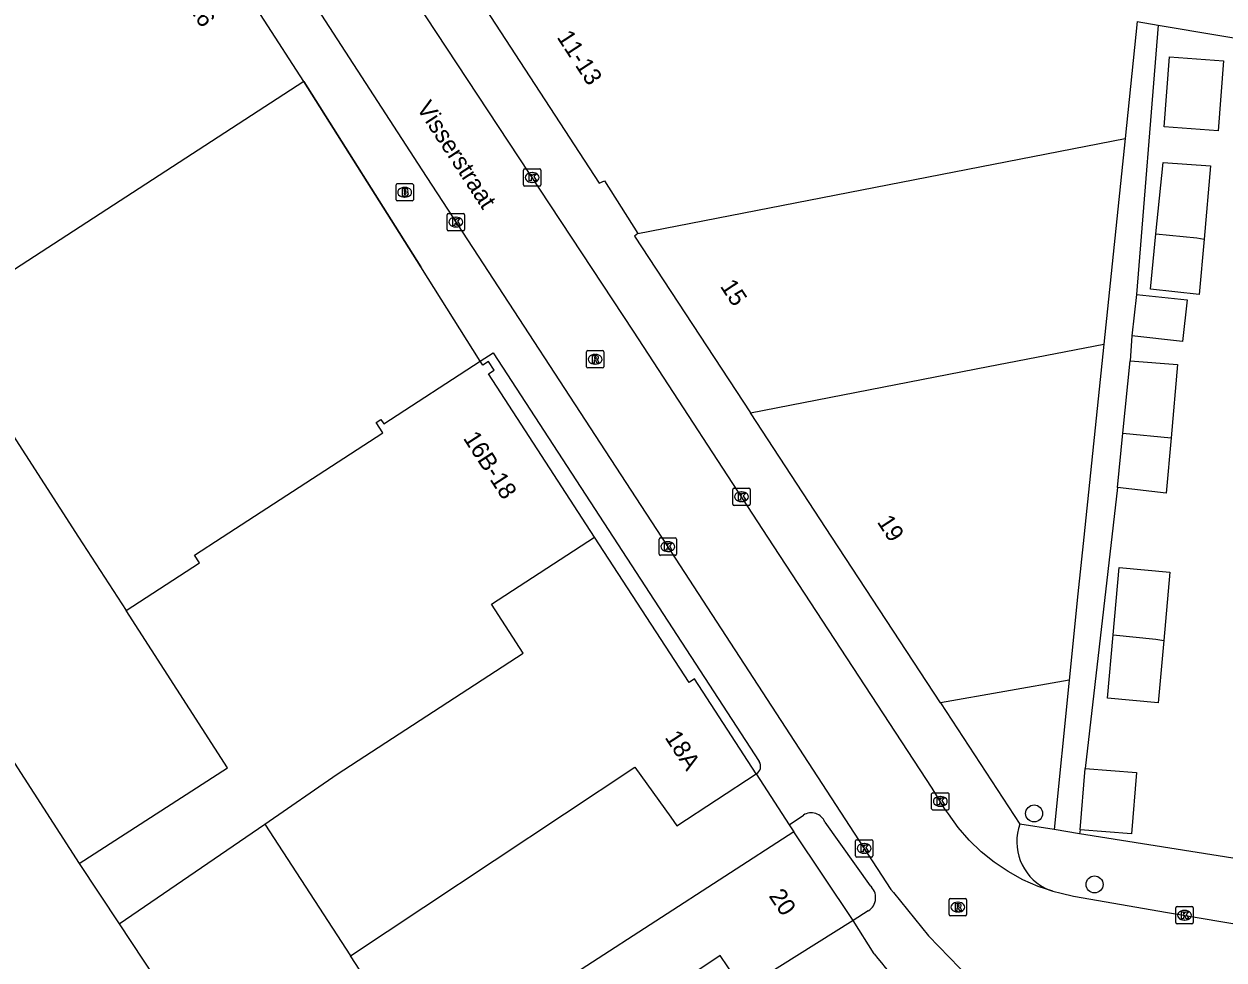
# Model space of a CAD drawing. Extents: x 160861 to 161308, y 384024 to 384878.
# Drawn here: x 161083.4 to 161152.6, y 384475.6 to 384529.6 of the extents above; entities that cross this region are included whole.
import ezdxf

# ---------------------------------------------------------------- set-up
doc = ezdxf.new("R2010")
doc.units = 0
for name, color, linetype in [('IMGEO_Boom', 7, 'Continuous'), ('IMGEO_Brandkraan', 7, 'Continuous'), ('IMGEO_Kolk', 7, 'Continuous'), ('IMGEO_Muur', 7, 'Continuous'), ('IMGEO_Openbare_ruimte_label', 7, 'Continuous'), ('IMGEO_Pand', 7, 'Continuous'), ('IMGEO_Pand_nummerreeks', 7, 'Continuous'), ('IMGEO_Parkeervlak_open', 7, 'Continuous'), ('IMGEO_Rijbaan_lokaal_open', 7, 'Continuous'), ('IMGEO_Rioolput', 7, 'Continuous'), ('IMGEO_Voetpad_open', 7, 'Continuous')]:
    doc.layers.add(name, color=color, linetype=linetype)

msp = doc.modelspace()

# ---------------------------------------------------------------- linework, layer by layer
at = {"layer": 'IMGEO_Boom'}
for centre in [(161141.654, 384484.053), (161145.139, 384479.956)]:
    msp.add_circle(centre, 0.489, dxfattribs=at)
at = {"layer": 'IMGEO_Brandkraan'}
for p, q in [((161104.842, 384519.474), (161104.842, 384520.326)), ((161104.917, 384520.4), (161105.769, 384520.4)), ((161105.33, 384520.18), (161105.355, 384520.18)), ((161105.843, 384520.326), (161105.843, 384519.474)), ((161105.353, 384519.62), (161105.328, 384519.62)), ((161105.769, 384519.4), (161104.917, 384519.4))]:
    msp.add_line(p, q, dxfattribs=at)
for points in [[(161104.842, 384519.474), (161104.842, 384520.326)], [(161104.917, 384520.4), (161105.769, 384520.4)], [(161105.843, 384520.326), (161105.843, 384519.474)], [(161105.19, 384520.1), (161105.19, 384519.7), (161105.403, 384519.7)], [(161105.421, 384520.1), (161105.19, 384520.1)], [(161105.369, 384520.019), (161105.315, 384520.019), (161105.315, 384519.943)], [(161105.315, 384519.943), (161105.368, 384519.943)], [(161105.377, 384519.867), (161105.315, 384519.867), (161105.315, 384519.786)], [(161105.315, 384519.786), (161105.377, 384519.786)], [(161105.769, 384519.4), (161104.917, 384519.4)]]:
    msp.add_lwpolyline(points, dxfattribs=at)
for centre, radius, start, end in [((161104.919, 384520.324), 0.0765, 91.55205, 178.44795), ((161104.919, 384520.324), 0.0765, 91.55205, 178.44795), ((161105.767, 384520.324), 0.0765, 1.55205, 88.44795), ((161105.767, 384520.324), 0.0765, 1.55205, 88.44795), ((161104.919, 384519.476), 0.0765, 181.55205, 268.44795), ((161104.919, 384519.476), 0.0765, 181.55205, 268.44795), ((161105.37, 384519.981), 0.0379, 267.82845, 90.93552), ((161105.378, 384519.826), 0.0404, 269.87594, 90.50774), ((161105.409, 384519.951), 0.251, 268.66757, 293.53466), ((161105.425, 384519.955), 0.145, 59.4692, 91.53667), ((161105.45, 384520.002), 0.0922, 285.51372, 58.15012), ((161105.455, 384519.81), 0.105, 301.31148, 78.98903), ((161105.767, 384519.476), 0.0765, 271.55205, 358.44795), ((161105.767, 384519.476), 0.0765, 271.55205, 358.44795)]:
    msp.add_arc(centre, radius, start, end, dxfattribs=at)
for centre, major_axis, ratio, start_param, end_param in [((161105.329, 384519.9), (-0.387, 0.002), 0.722429, 4.712389, 7.853982), ((161105.354, 384519.9), (-0.39, 0.002), 0.717154, 1.570796, 4.712389)]:
    msp.add_ellipse(centre, major_axis=major_axis, ratio=ratio, start_param=start_param, end_param=end_param, dxfattribs=at)
at = {"layer": 'IMGEO_Kolk'}
for p, q in [((161112.2, 384520.328), (161112.2, 384521.18)), ((161112.275, 384521.254), (161113.127, 384521.254)), ((161112.688, 384521.034), (161112.713, 384521.034)), ((161113.201, 384521.18), (161113.201, 384520.328)), ((161113.127, 384520.254), (161112.275, 384520.254)), ((161112.711, 384520.474), (161112.686, 384520.474)), ((161107.791, 384517.756), (161107.791, 384518.608)), ((161107.866, 384518.682), (161108.718, 384518.682)), ((161108.279, 384518.462), (161108.304, 384518.462)), ((161108.792, 384518.608), (161108.792, 384517.756)), ((161108.718, 384517.682), (161107.866, 384517.682)), ((161108.302, 384517.902), (161108.277, 384517.902)), ((161124.352, 384502.83), (161125.204, 384502.83)), ((161124.277, 384501.904), (161124.277, 384502.756)), ((161124.765, 384502.61), (161124.79, 384502.61)), ((161125.278, 384502.756), (161125.278, 384501.904)), ((161125.204, 384501.83), (161124.352, 384501.83)), ((161124.788, 384502.05), (161124.763, 384502.05)), ((161120.018, 384499.022), (161120.018, 384499.874)), ((161120.093, 384499.948), (161120.945, 384499.948)), ((161120.506, 384499.728), (161120.531, 384499.728)), ((161121.019, 384499.874), (161121.019, 384499.022)), ((161120.945, 384498.948), (161120.093, 384498.948)), ((161120.529, 384499.168), (161120.504, 384499.168)), ((161135.742, 384484.322), (161135.742, 384485.174)), ((161135.817, 384485.248), (161136.669, 384485.248)), ((161136.23, 384485.028), (161136.255, 384485.028)), ((161136.743, 384485.174), (161136.743, 384484.322)), ((161136.669, 384484.248), (161135.817, 384484.248)), ((161136.253, 384484.468), (161136.228, 384484.468)), ((161131.353, 384481.609), (161131.353, 384482.461)), ((161131.428, 384482.535), (161132.28, 384482.535)), ((161131.841, 384482.315), (161131.866, 384482.315)), ((161132.354, 384482.461), (161132.354, 384481.609)), ((161132.28, 384481.535), (161131.428, 384481.535)), ((161131.864, 384481.755), (161131.839, 384481.755)), ((161149.832, 384477.749), (161149.832, 384478.601)), ((161149.907, 384478.675), (161150.759, 384478.675)), ((161150.833, 384478.601), (161150.833, 384477.749)), ((161150.32, 384478.455), (161150.345, 384478.455)), ((161150.759, 384477.675), (161149.907, 384477.675)), ((161150.343, 384477.895), (161150.318, 384477.895))]:
    msp.add_line(p, q, dxfattribs=at)
for points in [[(161112.2, 384520.328), (161112.2, 384521.18)], [(161112.275, 384521.254), (161113.127, 384521.254)], [(161112.521, 384520.954), (161112.644, 384520.954), (161112.644, 384520.803), (161112.774, 384520.954), (161112.938, 384520.954), (161112.792, 384520.803), (161112.945, 384520.554), (161112.793, 384520.554), (161112.708, 384520.718), (161112.644, 384520.651), (161112.644, 384520.554), (161112.521, 384520.554), (161112.521, 384520.954)], [(161113.201, 384521.18), (161113.201, 384520.328)], [(161113.127, 384520.254), (161112.275, 384520.254)], [(161107.791, 384517.756), (161107.791, 384518.608)], [(161107.866, 384518.682), (161108.718, 384518.682)], [(161108.112, 384518.382), (161108.235, 384518.382), (161108.235, 384518.231), (161108.365, 384518.382), (161108.529, 384518.382), (161108.383, 384518.231), (161108.536, 384517.982), (161108.384, 384517.982), (161108.299, 384518.146), (161108.235, 384518.079), (161108.235, 384517.982), (161108.112, 384517.982), (161108.112, 384518.382)], [(161108.792, 384518.608), (161108.792, 384517.756)], [(161108.718, 384517.682), (161107.866, 384517.682)], [(161124.352, 384502.83), (161125.204, 384502.83)], [(161124.277, 384501.904), (161124.277, 384502.756)], [(161124.598, 384502.53), (161124.721, 384502.53), (161124.721, 384502.379), (161124.851, 384502.53), (161125.015, 384502.53), (161124.869, 384502.379), (161125.022, 384502.13), (161124.87, 384502.13), (161124.785, 384502.294), (161124.721, 384502.227), (161124.721, 384502.13), (161124.598, 384502.13), (161124.598, 384502.53)], [(161125.278, 384502.756), (161125.278, 384501.904)], [(161125.204, 384501.83), (161124.352, 384501.83)], [(161120.018, 384499.022), (161120.018, 384499.874)], [(161120.093, 384499.948), (161120.945, 384499.948)], [(161120.339, 384499.648), (161120.462, 384499.648), (161120.462, 384499.497), (161120.592, 384499.648), (161120.756, 384499.648), (161120.61, 384499.497), (161120.763, 384499.248), (161120.611, 384499.248), (161120.526, 384499.412), (161120.462, 384499.345), (161120.462, 384499.248), (161120.339, 384499.248), (161120.339, 384499.648)], [(161121.019, 384499.874), (161121.019, 384499.022)], [(161120.945, 384498.948), (161120.093, 384498.948)], [(161135.742, 384484.322), (161135.742, 384485.174)], [(161135.817, 384485.248), (161136.669, 384485.248)], [(161136.063, 384484.948), (161136.186, 384484.948), (161136.186, 384484.797), (161136.316, 384484.948), (161136.48, 384484.948), (161136.334, 384484.797), (161136.487, 384484.548), (161136.335, 384484.548), (161136.25, 384484.712), (161136.186, 384484.645), (161136.186, 384484.548), (161136.063, 384484.548), (161136.063, 384484.948)], [(161136.743, 384485.174), (161136.743, 384484.322)], [(161136.669, 384484.248), (161135.817, 384484.248)], [(161131.353, 384481.609), (161131.353, 384482.461)], [(161131.428, 384482.535), (161132.28, 384482.535)], [(161131.674, 384482.235), (161131.797, 384482.235), (161131.797, 384482.084), (161131.927, 384482.235), (161132.091, 384482.235), (161131.945, 384482.084), (161132.098, 384481.835), (161131.946, 384481.835), (161131.861, 384481.999), (161131.797, 384481.932), (161131.797, 384481.835), (161131.674, 384481.835), (161131.674, 384482.235)], [(161132.354, 384482.461), (161132.354, 384481.609)], [(161132.28, 384481.535), (161131.428, 384481.535)], [(161149.832, 384477.749), (161149.832, 384478.601)], [(161149.907, 384478.675), (161150.759, 384478.675)], [(161150.833, 384478.601), (161150.833, 384477.749)], [(161150.153, 384478.375), (161150.276, 384478.375), (161150.276, 384478.224), (161150.406, 384478.375), (161150.57, 384478.375), (161150.424, 384478.224), (161150.577, 384477.975), (161150.425, 384477.975), (161150.34, 384478.139), (161150.276, 384478.072), (161150.276, 384477.975), (161150.153, 384477.975), (161150.153, 384478.375)], [(161150.759, 384477.675), (161149.907, 384477.675)]]:
    msp.add_lwpolyline(points, dxfattribs=at)
for centre, start, end in [((161112.277, 384521.178), 91.55205, 178.44795), ((161112.277, 384521.178), 91.55205, 178.44795), ((161113.125, 384521.178), 1.55205, 88.44795), ((161113.125, 384521.178), 1.55205, 88.44795), ((161112.277, 384520.33), 181.55205, 268.44795), ((161112.277, 384520.33), 181.55205, 268.44795), ((161113.125, 384520.33), 271.55205, 358.44795), ((161113.125, 384520.33), 271.55205, 358.44795), ((161107.868, 384518.606), 91.55205, 178.44795), ((161107.868, 384518.606), 91.55205, 178.44795), ((161108.716, 384518.606), 1.55205, 88.44795), ((161108.716, 384518.606), 1.55205, 88.44795), ((161107.868, 384517.758), 181.55205, 268.44795), ((161107.868, 384517.758), 181.55205, 268.44795), ((161108.716, 384517.758), 271.55205, 358.44795), ((161108.716, 384517.758), 271.55205, 358.44795), ((161124.354, 384502.754), 91.55205, 178.44795), ((161124.354, 384502.754), 91.55205, 178.44795), ((161125.202, 384502.754), 1.55205, 88.44795), ((161125.202, 384502.754), 1.55205, 88.44795), ((161124.354, 384501.906), 181.55205, 268.44795), ((161124.354, 384501.906), 181.55205, 268.44795), ((161125.202, 384501.906), 271.55205, 358.44795), ((161125.202, 384501.906), 271.55205, 358.44795), ((161120.095, 384499.872), 91.55205, 178.44795), ((161120.095, 384499.872), 91.55205, 178.44795), ((161120.943, 384499.872), 1.55205, 88.44795), ((161120.943, 384499.872), 1.55205, 88.44795), ((161120.095, 384499.024), 181.55205, 268.44795), ((161120.095, 384499.024), 181.55205, 268.44795), ((161120.943, 384499.024), 271.55205, 358.44795), ((161120.943, 384499.024), 271.55205, 358.44795), ((161135.819, 384485.172), 91.55205, 178.44795), ((161135.819, 384485.172), 91.55205, 178.44795), ((161136.667, 384485.172), 1.55205, 88.44795), ((161136.667, 384485.172), 1.55205, 88.44795), ((161135.819, 384484.324), 181.55205, 268.44795), ((161135.819, 384484.324), 181.55205, 268.44795), ((161136.667, 384484.324), 271.55205, 358.44795), ((161136.667, 384484.324), 271.55205, 358.44795), ((161131.43, 384482.459), 91.55205, 178.44795), ((161131.43, 384482.459), 91.55205, 178.44795), ((161132.278, 384482.459), 1.55205, 88.44795), ((161132.278, 384482.459), 1.55205, 88.44795), ((161131.43, 384481.611), 181.55205, 268.44795), ((161131.43, 384481.611), 181.55205, 268.44795), ((161132.278, 384481.611), 271.55205, 358.44795), ((161132.278, 384481.611), 271.55205, 358.44795), ((161149.909, 384478.599), 91.55205, 178.44795), ((161149.909, 384478.599), 91.55205, 178.44795), ((161150.757, 384478.599), 1.55205, 88.44795), ((161150.757, 384478.599), 1.55205, 88.44795), ((161149.909, 384477.751), 181.55205, 268.44795), ((161149.909, 384477.751), 181.55205, 268.44795), ((161150.757, 384477.751), 271.55205, 358.44795), ((161150.757, 384477.751), 271.55205, 358.44795)]:
    msp.add_arc(centre, 0.0765, start, end, dxfattribs=at)
for centre, major_axis, ratio, start_param, end_param in [((161112.687, 384520.754), (-0.387, 0.002), 0.722429, 4.712389, 7.853982), ((161112.712, 384520.754), (-0.39, 0.002), 0.717154, 1.570796, 4.712389), ((161108.278, 384518.182), (-0.387, 0.002), 0.722429, 4.712389, 7.853982), ((161108.303, 384518.182), (-0.39, 0.002), 0.717154, 1.570796, 4.712389), ((161124.764, 384502.33), (-0.387, 0.002), 0.722429, 4.712389, 7.853982), ((161124.789, 384502.33), (-0.39, 0.002), 0.717154, 1.570796, 4.712389), ((161120.505, 384499.448), (-0.387, 0.002), 0.722429, 4.712389, 7.853982), ((161120.53, 384499.448), (-0.39, 0.002), 0.717154, 1.570796, 4.712389), ((161136.229, 384484.748), (-0.387, 0.002), 0.722429, 4.712389, 7.853982), ((161136.254, 384484.748), (-0.39, 0.002), 0.717154, 1.570796, 4.712389), ((161131.84, 384482.035), (-0.387, 0.002), 0.722429, 4.712389, 7.853982), ((161131.865, 384482.035), (-0.39, 0.002), 0.717154, 1.570796, 4.712389), ((161150.319, 384478.175), (-0.387, 0.002), 0.722429, 4.712389, 7.853982), ((161150.344, 384478.175), (-0.39, 0.002), 0.717154, 1.570796, 4.712389)]:
    msp.add_ellipse(centre, major_axis=major_axis, ratio=ratio, start_param=start_param, end_param=end_param, dxfattribs=at)
at = {"layer": 'IMGEO_Muur'}
msp.add_lwpolyline([(161099.532, 384526.285), (161106.274, 384515.593)], dxfattribs=at)
at = {"layer": 'IMGEO_Pand'}
for points in [[(161099.532, 384526.285), (161092.65, 384536.939)], [(161108.586, 384536.5), (161108.284, 384533.515), (161110.201, 384530.752), (161110.014, 384530.492), (161116.568, 384520.434), (161116.865, 384520.568), (161118.791, 384517.525)], [(161147.595, 384529.749), (161146.897, 384522.997)], [(161149.148, 384523.684), (161149.461, 384527.721), (161152.575, 384527.48), (161152.263, 384523.443), (161149.148, 384523.684)], [(161099.532, 384526.285), (161078.632, 384512.731), (161078.403, 384512.582)], [(161118.791, 384517.525), (161146.897, 384522.997)], [(161146.897, 384522.997), (161145.671, 384511.135)], [(161148.683, 384517.506), (161149.099, 384521.62), (161151.828, 384521.418), (161151.459, 384517.196)], [(161118.791, 384517.525), (161118.6, 384517.368), (161125.289, 384507.167)], [(161151.459, 384517.196), (161151.179, 384513.998), (161148.36, 384514.309), (161148.683, 384517.506)], [(161148.683, 384517.506), (161151.033, 384517.267), (161151.459, 384517.196)], [(161147.564, 384514.007), (161147.3, 384511.615)], [(161147.564, 384514.007), (161150.475, 384513.686), (161150.211, 384511.294), (161147.3, 384511.615)], [(161078.403, 384512.582), (161086.528, 384500), (161089.266, 384495.761)], [(161125.289, 384507.167), (161139.008, 384509.838), (161145.671, 384511.135)], [(161145.671, 384511.135), (161144.52, 384500), (161144.181, 384496.717), (161143.676, 384491.742)], [(161089.266, 384495.761), (161093.508, 384498.519), (161093.22, 384498.961), (161094.818, 384500), (161104.086, 384506.027), (161103.703, 384506.616), (161103.966, 384506.787), (161104.133, 384506.531), (161109.703, 384510.154)], [(161116.298, 384500), (161110.176, 384509.414), (161110.505, 384509.628), (161110.173, 384510.137), (161109.85, 384509.927), (161109.703, 384510.154)], [(161146.778, 384506.004), (161147.199, 384510.164)], [(161147.199, 384510.164), (161149.928, 384509.962), (161149.557, 384505.722)], [(161069.859, 384507.042), (161070.066, 384506.722), (161074.406, 384500), (161086.57, 384481.163)], [(161136.26, 384490.435), (161129.988, 384500), (161125.289, 384507.167)], [(161146.46, 384502.853), (161146.778, 384506.004)], [(161149.557, 384505.722), (161149.279, 384502.542), (161146.46, 384502.853)], [(161146.778, 384506.004), (161149.557, 384505.722)], [(161097.269, 384483.441), (161101.448, 384486.31), (161112.184, 384493.292), (161110.342, 384496.125), (161116.298, 384500)], [(161125.626, 384486.329), (161122.06, 384491.813), (161121.753, 384491.613), (161116.298, 384500)], [(161146.214, 384494.367), (161146.564, 384498.248), (161149.492, 384497.984), (161149.136, 384494.04)], [(161086.57, 384481.163), (161095.125, 384486.687), (161089.266, 384495.761)], [(161149.136, 384494.04), (161148.811, 384490.44), (161145.884, 384490.704), (161146.214, 384494.367)], [(161146.214, 384494.367), (161148.673, 384494.117), (161149.136, 384494.04)], [(161143.676, 384491.742), (161136.26, 384490.435)], [(161102.22, 384475.828), (161106.441, 384478.633), (161118.625, 384486.727), (161120.689, 384483.829), (161121.035, 384483.343), (161125.626, 384486.329)], [(161144.317, 384483.115), (161144.606, 384486.647)], [(161144.606, 384486.647), (161147.568, 384486.405), (161147.279, 384482.873), (161144.317, 384483.115)], [(161088.869, 384477.676), (161097.269, 384483.441)], [(161097.269, 384483.441), (161102.22, 384475.828)], [(161127.791, 384482.982), (161107.881, 384470.092)], [(161131.213, 384477.878), (161127.791, 384482.982)], [(161086.57, 384481.163), (161088.869, 384477.676)], [(161088.869, 384477.676), (161097.209, 384465.039)], [(161131.213, 384477.878), (161124.863, 384473.882), (161123.536, 384475.861), (161119.134, 384472.91), (161117.964, 384474.654), (161116.386, 384473.596), (161118.168, 384470.938), (161109.942, 384465.677)], [(161106.522, 384469.213), (161102.22, 384475.828)]]:
    msp.add_lwpolyline(points, dxfattribs=at)
at = {"layer": 'IMGEO_Parkeervlak_open'}
for points in [[(161109.703, 384510.154), (161106.274, 384515.593), (161099.532, 384526.285)], [(161136.26, 384490.435), (161140.833, 384483.433)], [(161125.626, 384486.329), (161127.519, 384483.402)], [(161132.428, 384475.949), (161131.213, 384477.878)]]:
    msp.add_lwpolyline(points, dxfattribs=at)
msp.add_arc((161157.697, 384495.628), 32.028, 217.91021, 237.04576, dxfattribs=at)
at = {"layer": 'IMGEO_Rijbaan_lokaal_open'}
for points in [[(161096.1, 384536.996), (161106.333, 384521.187), (161120.155, 384500), (161133.397, 384479.667), (161133.535, 384479.496), (161135.559, 384476.994), (161137.951, 384474.526), (161140.555, 384472.281), (161143.348, 384470.277), (161145.038, 384469.237), (161146.601, 384468.302), (161147.548, 384467.735)], [(161142.726, 384479.56), (161141.89, 384479.842), (161141.004, 384480.229), (161140.156, 384480.693), (161139.353, 384481.23), (161138.602, 384481.838), (161137.907, 384482.51), (161137.276, 384483.241), (161136.712, 384484.026), (161136.487, 384484.329), (161135.763, 384485.512), (161126.296, 384500), (161118.543, 384511.891), (161101.766, 384537.337)], [(161142.726, 384479.56), (161143.205, 384479.449), (161143.93, 384479.281), (161149.357, 384478.328), (161159.505, 384476.619), (161164.111, 384475.857)]]:
    msp.add_lwpolyline(points, dxfattribs=at)
at = {"layer": 'IMGEO_Rioolput'}
for p, q in [((161115.829, 384509.835), (161115.829, 384510.687)), ((161115.904, 384510.761), (161116.756, 384510.761)), ((161116.317, 384510.541), (161116.342, 384510.541)), ((161116.83, 384510.687), (161116.83, 384509.835)), ((161116.756, 384509.761), (161115.904, 384509.761)), ((161116.34, 384509.981), (161116.315, 384509.981)), ((161136.756, 384478.218), (161136.756, 384479.07)), ((161136.831, 384479.144), (161137.683, 384479.144)), ((161137.244, 384478.924), (161137.269, 384478.924)), ((161137.757, 384479.07), (161137.757, 384478.218)), ((161137.683, 384478.144), (161136.831, 384478.144)), ((161137.267, 384478.364), (161137.242, 384478.364))]:
    msp.add_line(p, q, dxfattribs=at)
for points in [[(161115.829, 384509.835), (161115.829, 384510.687)], [(161115.904, 384510.761), (161116.756, 384510.761)], [(161116.418, 384510.459), (161116.166, 384510.461), (161116.166, 384510.061)], [(161116.83, 384510.687), (161116.83, 384509.835)], [(161116.756, 384509.761), (161115.904, 384509.761)], [(161116.166, 384510.061), (161116.29, 384510.061), (161116.29, 384510.223), (161116.301, 384510.223)], [(161116.344, 384510.38), (161116.29, 384510.38), (161116.29, 384510.299)], [(161116.29, 384510.299), (161116.342, 384510.299)], [(161116.348, 384510.194), (161116.419, 384510.061), (161116.559, 384510.061), (161116.494, 384510.187)], [(161136.756, 384478.218), (161136.756, 384479.07)], [(161136.831, 384479.144), (161137.683, 384479.144)], [(161137.345, 384478.842), (161137.093, 384478.844), (161137.093, 384478.444)], [(161137.093, 384478.444), (161137.217, 384478.444), (161137.217, 384478.606), (161137.228, 384478.606)], [(161137.271, 384478.763), (161137.217, 384478.763), (161137.217, 384478.682)], [(161137.217, 384478.682), (161137.269, 384478.682)], [(161137.757, 384479.07), (161137.757, 384478.218)], [(161137.683, 384478.144), (161136.831, 384478.144)], [(161137.275, 384478.577), (161137.346, 384478.444), (161137.486, 384478.444), (161137.421, 384478.57)]]:
    msp.add_lwpolyline(points, dxfattribs=at)
for centre, radius, start, end in [((161115.906, 384510.685), 0.0765, 91.55205, 178.44795), ((161115.906, 384510.685), 0.0765, 91.55205, 178.44795), ((161116.417, 384510.349), 0.109, 350.36119, 89.41601), ((161116.754, 384510.685), 0.0765, 1.55205, 88.44795), ((161116.754, 384510.685), 0.0765, 1.55205, 88.44795), ((161115.906, 384509.837), 0.0765, 181.55205, 268.44795), ((161115.906, 384509.837), 0.0765, 181.55205, 268.44795), ((161116.3, 384510.17), 0.0533, 26.02933, 88.69889), ((161116.326, 384510.488), 0.19, 274.7715, 282.96867), ((161116.35, 384510.284), 0.0964, 77.00612, 93.18647), ((161116.364, 384510.341), 0.0378, 276.66336, 79.67722), ((161116.415, 384510.349), 0.112, 277.58423, 350.98172), ((161116.399, 384510.134), 0.108, 29.51342, 73.79051), ((161116.754, 384509.837), 0.0765, 271.55205, 358.44795), ((161116.754, 384509.837), 0.0765, 271.55205, 358.44795), ((161136.833, 384479.068), 0.0765, 91.55205, 178.44795), ((161136.833, 384479.068), 0.0765, 91.55205, 178.44795), ((161137.227, 384478.553), 0.0533, 26.02933, 88.69889), ((161137.253, 384478.871), 0.19, 274.7715, 282.96867), ((161137.277, 384478.667), 0.0964, 77.00612, 93.18647), ((161137.291, 384478.724), 0.0378, 276.66336, 79.67722), ((161137.344, 384478.732), 0.109, 350.36119, 89.41601), ((161137.342, 384478.732), 0.112, 277.58423, 350.98172), ((161137.326, 384478.517), 0.108, 29.51342, 73.79051), ((161137.681, 384479.068), 0.0765, 1.55205, 88.44795), ((161137.681, 384479.068), 0.0765, 1.55205, 88.44795), ((161136.833, 384478.22), 0.0765, 181.55205, 268.44795), ((161136.833, 384478.22), 0.0765, 181.55205, 268.44795), ((161137.681, 384478.22), 0.0765, 271.55205, 358.44795), ((161137.681, 384478.22), 0.0765, 271.55205, 358.44795)]:
    msp.add_arc(centre, radius, start, end, dxfattribs=at)
for centre, major_axis, ratio, start_param, end_param in [((161116.316, 384510.261), (-0.387, 0.002), 0.722429, 4.712389, 7.853982), ((161116.341, 384510.261), (-0.39, 0.002), 0.717154, 1.570796, 4.712389), ((161137.243, 384478.644), (-0.387, 0.002), 0.722429, 4.712389, 7.853982), ((161137.268, 384478.644), (-0.39, 0.002), 0.717154, 1.570796, 4.712389)]:
    msp.add_ellipse(centre, major_axis=major_axis, ratio=ratio, start_param=start_param, end_param=end_param, dxfattribs=at)
at = {"layer": 'IMGEO_Voetpad_open'}
for points in [[(161148.815, 384529.545), (161147.564, 384514.007)], [(161147.595, 384529.749), (161148.815, 384529.545)], [(161148.815, 384529.545), (161163.276, 384527.128)], [(161147.3, 384511.615), (161147.199, 384510.164)], [(161109.703, 384510.154), (161110.453, 384510.641), (161117.372, 384500), (161125.793, 384487.05)], [(161146.46, 384502.853), (161144.606, 384486.647)], [(161143.676, 384491.742), (161142.816, 384483.117)], [(161127.519, 384483.402), (161128.344, 384483.955)], [(161129.587, 384483.55), (161132.193, 384479.881)], [(161127.519, 384483.402), (161127.791, 384482.982)], [(161140.833, 384483.433), (161140.753, 384483.177), (161140.697, 384482.914), (161140.664, 384482.648), (161140.655, 384482.379), (161140.67, 384482.111), (161140.709, 384481.845), (161140.772, 384481.584), (161140.858, 384481.33), (161140.966, 384481.084), (161141.095, 384480.849), (161141.246, 384480.626), (161141.415, 384480.418), (161141.602, 384480.226), (161141.806, 384480.051), (161142.025, 384479.895), (161142.256, 384479.759), (161142.499, 384479.644), (161142.726, 384479.56)], [(161142.816, 384483.117), (161140.833, 384483.433)], [(161144.28, 384482.884), (161142.816, 384483.117)], [(161144.317, 384483.115), (161144.28, 384482.884)], [(161159.147, 384480.487), (161157.474, 384480.784), (161144.28, 384482.884)], [(161132.085, 384478.427), (161131.213, 384477.878)]]:
    msp.add_lwpolyline(points, dxfattribs=at)
for centre, radius, start, end in [((161125.36, 384486.771), 0.516, 301.08942, 32.82851), ((161128.794, 384483.227), 0.856, 22.17405, 121.73219), ((161131.61, 384479.193), 0.902, 301.80964, 49.69435)]:
    msp.add_arc(centre, radius, start, end, dxfattribs=at)

# ---------------------------------------------------------------- texts
at = {"layer": 'IMGEO_Openbare_ruimte_label'}
msp.add_text('Visserstraat', height=1, rotation=303.08631, dxfattribs=at).set_placement((161105.998, 384524.767))
at = {"layer": 'IMGEO_Pand_nummerreeks'}
for s, rotation, p in [('16', 302.94486, (161092.821, 384530.588)), ('11-13', 303.0881, (161114.091, 384528.851)), ('15', 303.25366, (161123.508, 384514.48)), ('16B-18', 302.92704, (161108.687, 384505.707)), ('19', 303.20037, (161132.563, 384500.876)), ('18A', 302.99027, (161120.319, 384488.439)), ('20', 303.84006, (161126.319, 384479.287))]:
    msp.add_text(s, height=1, rotation=rotation, dxfattribs=at).set_placement(p)

doc.saveas('drawing.dxf')
